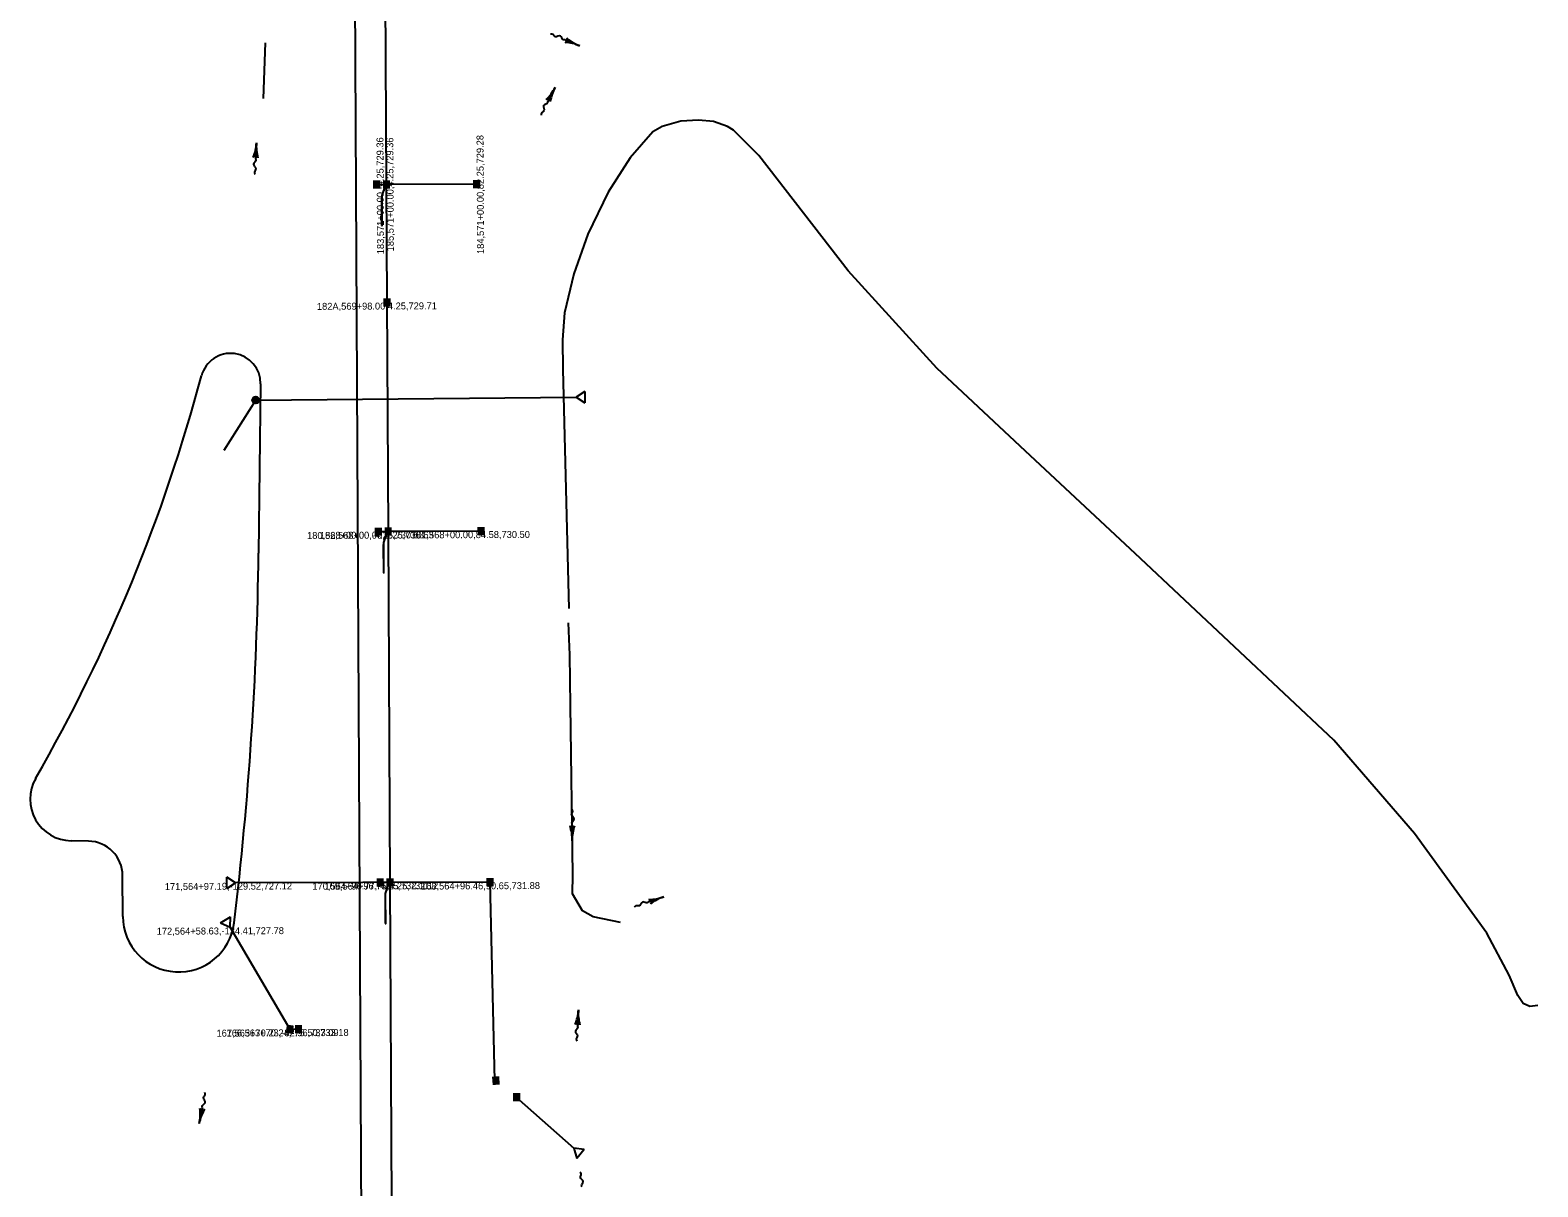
# Model space of a CAD drawing. Extents: x 593481 to 595859, y 101157 to 225994.
# Drawn here: x 594042 to 595346, y 155509 to 156509 of the extents above; entities that cross this region are included whole.
import ezdxf

# ---------------------------------------------------------------- set-up
doc = ezdxf.new("R2010")
doc.units = 0
for name, color, linetype in [('Default', 7, 'Continuous'), ('E_DTM_SpotElev', 7, 'Continuous'), ('E_PROF_GridMin', 7, 'Continuous'), ('Level 6', 7, 'Continuous'), ('P_DRN_SS_UG', 7, 'Continuous'), ('P_MAP_ContoursIndex', 7, 'Continuous'), ('P_MAP_ContoursInter', 7, 'Continuous'), ('P_RDWY_C_and_G_H', 7, 'Continuous')]:
    doc.layers.add(name, color=color, linetype=linetype)

msp = doc.modelspace()

# ---------------------------------------------------------------- linework, layer by layer
at = {"layer": 'Default'}
msp.add_line((594334.5, 154382.7), (594308.8, 159385.6), dxfattribs=at)
at = {"layer": 'E_DTM_SpotElev'}
for p, q in [((594517.4, 156495), (594504.3, 156500.4)), ((594496.2, 156459.2), (594489.7, 156446.7)), ((594238, 156411.3), (594237.2, 156397.2)), ((594510.9, 155808.1), (594511, 155822.3)), ((594590.1, 155759.5), (594576.7, 155755)), ((594516.3, 155661.9), (594515.5, 155647.8)), ((594188.6, 155563.7), (594191.3, 155577.6))]:
    msp.add_line(p, q, dxfattribs=at)
for points in [[(594504.8, 156498.1), (594508.5, 156498.7), (594506.3, 156501.8)], [(594492.1, 156446.9), (594491.8, 156450.7), (594488.6, 156448.8)], [(594239.3, 156398.4), (594237.5, 156401.7), (594235.3, 156398.6)], [(594509, 155820.9), (594511, 155817.7), (594513, 155820.9)], [(594578.6, 155753.5), (594581, 155756.5), (594577.3, 155757.3)], [(594517.6, 155649), (594515.7, 155652.3), (594513.6, 155649.2)], [(594189.1, 155576.7), (594190.4, 155573.2), (594193, 155575.9)]]:
    msp.add_lwpolyline(points, dxfattribs=at)
for centre, start, end in [((594533.4, 156533.8), 229.7798, 247.5421), ((594501.4, 156456.3), 67.5421, 85.3044), ((594458.8, 156478.3), 315.1931, 332.9554), ((594533.5, 156440.2), 152.9554, 170.7177), ((594196.1, 156413.6), 339.0322, 356.7946), ((594279.9, 156408.9), 176.7946, 194.5569), ((594469, 155808.4), 359.6117, 17.374), ((594552.9, 155807.9), 161.8494, 179.6117), ((594576.8, 155799.3), 270.74, 288.5023), ((594603.4, 155719.7), 108.5023, 126.2646), ((594474.4, 155664.2), 339.0322, 356.7946), ((594558.2, 155659.5), 176.7946, 194.5569), ((594147.4, 155571.7), 349.0067, 6.769), ((594229.8, 155555.7), 151.2443, 169.0067)]:
    msp.add_arc(centre, 42, start, end, dxfattribs=at)
for points in [[(594504.3, 156500.4), (594503.5, 156500.4), (594500.9, 156503.6), (594496.4, 156503), (594494.2, 156505), (594492.3, 156505.1)], [(594489.7, 156446.7), (594489.7, 156445.8), (594486.3, 156443.5), (594486.5, 156439), (594484.4, 156436.9), (594484.2, 156435.1)], [(594237.2, 156397.2), (594237.5, 156396.4), (594235.4, 156392.9), (594237.4, 156388.8), (594236.3, 156386), (594236.8, 156384.3)], [(594511, 155822.3), (594510.7, 155823.1), (594512.6, 155826.7), (594510.5, 155830.6), (594511.4, 155833.4), (594510.8, 155835.1)], [(594576.7, 155755), (594576, 155754.5), (594572, 155755.1), (594569, 155751.8), (594566, 155751.8), (594564.6, 155750.6)], [(594515.5, 155647.8), (594515.8, 155647), (594513.7, 155643.5), (594515.6, 155639.4), (594514.5, 155636.7), (594515.1, 155634.9)], [(594191.3, 155577.6), (594191.1, 155578.4), (594193.7, 155581.6), (594192.3, 155585.9), (594193.7, 155588.5), (594193.4, 155590.3)], [(594519.5, 155508.9), (594519.1, 155509.6), (594520.6, 155513.4), (594518.1, 155517.1), (594518.7, 155520), (594517.9, 155521.7)]]:
    msp.add_spline(points, degree=3, dxfattribs=at)
at = {"layer": 'E_PROF_GridMin'}
for p, q in [((594350.5, 156375.2), (594349, 156675.2)), ((594342, 156375.2), (594350.5, 156375.2)), ((594428.5, 156375.6), (594350.5, 156375.2)), ((594352.1, 156075.2), (594350.5, 156375.2)), ((594210.2, 156145.7), (594237.4, 156188.9)), ((594237.4, 156188.9), (594514.4, 156191.3)), ((594343.6, 156075.2), (594352.1, 156075.2)), ((594432.4, 156075.6), (594352.1, 156075.2)), ((594353.6, 155772), (594352.1, 156075.2)), ((594440, 155772.1), (594219.8, 155771.7)), ((594355, 155495.2), (594353.6, 155772)), ((594444.2, 155600.7), (594440, 155772.1)), ((594267.1, 155645), (594215.2, 155733.2)), ((594274.5, 155645.1), (594267, 155645)), ((594462.4, 155586.4), (594512.3, 155542.2))]:
    msp.add_line(p, q, dxfattribs=at)
for points in [[(594245.5, 156497.7), (594243.8, 156449.5)], [(595345.8, 155665.5), (595338.9, 155664.9), (595333.1, 155667.3), (595328.4, 155674.3), (595321, 155691.9), (595301.8, 155728.2), (595239.2, 155814.2), (595169.4, 155895), (594997.8, 156056.2), (594907.2, 156140.8), (594826.3, 156216.4), (594749.6, 156300.6), (594672.2, 156400.2), (594650.5, 156422.2), (594645.2, 156425.4), (594633, 156429.8), (594620.3, 156430.9), (594605, 156429.9), (594588.7, 156425.4), (594580.7, 156420.9), (594561, 156398.2), (594542.2, 156368.7), (594524.6, 156332.4), (594512.5, 156297.9), (594504.2, 156264.4), (594502.7, 156240.9), (594503, 156215.3), (594508, 156008.7)], [(594349.2, 156374.2), (594346.3, 156365.7), (594346.3, 156363.7)], [(594350.7, 156074.2), (594347.9, 156065.7), (594347.9, 156063.7)], [(594552.8, 155737.4), (594529.2, 155742.3), (594520, 155747.6), (594511.1, 155762.2), (594511.5, 155778.5), (594509.6, 155924.8), (594508.9, 155968.8), (594507.7, 155996.4)], [(594352.3, 155771), (594349.4, 155762.5), (594349.4, 155760.5)]]:
    msp.add_lwpolyline(points, dxfattribs=at)
at = {"layer": 'P_DRN_SS_UG'}
for p, q in [((594339.8, 156371.7), (594339.8, 156378.6)), ((594340.7, 156371.7), (594340.7, 156378.6)), ((594341.6, 156371.7), (594341.6, 156378.6)), ((594342.5, 156371.8), (594342.5, 156378.6)), ((594343.4, 156371.8), (594343.4, 156378.6)), ((594344.3, 156371.8), (594344.3, 156378.6)), ((594348.3, 156371.8), (594348.3, 156378.7)), ((594349.2, 156371.8), (594349.2, 156378.7)), ((594350.1, 156371.8), (594350.1, 156378.7)), ((594351, 156371.8), (594351, 156378.7)), ((594351.9, 156371.8), (594351.9, 156378.7)), ((594352.8, 156371.8), (594352.8, 156378.7)), ((594426.3, 156372.2), (594426.3, 156379.1)), ((594427.2, 156372.2), (594427.2, 156379.1)), ((594428.1, 156372.2), (594428.1, 156379.1)), ((594429, 156372.2), (594429, 156379.1)), ((594429.9, 156372.2), (594429.9, 156379.1)), ((594430.8, 156372.2), (594430.8, 156379.1)), ((594348.8, 156269.8), (594348.8, 156276.7)), ((594349.7, 156269.8), (594349.7, 156276.7)), ((594350.6, 156269.8), (594350.6, 156276.7)), ((594351.5, 156269.8), (594351.5, 156276.7)), ((594352.4, 156269.8), (594352.4, 156276.7)), ((594353.3, 156269.8), (594353.3, 156276.7)), ((594341.3, 156071.7), (594341.3, 156078.6)), ((594342.2, 156071.7), (594342.2, 156078.6)), ((594343.1, 156071.8), (594343.1, 156078.6)), ((594344, 156071.8), (594344, 156078.6)), ((594344.9, 156071.8), (594344.9, 156078.6)), ((594345.8, 156071.8), (594345.8, 156078.6)), ((594349.8, 156071.8), (594349.8, 156078.7)), ((594350.7, 156071.8), (594350.7, 156078.7)), ((594351.6, 156071.8), (594351.6, 156078.7)), ((594352.5, 156071.8), (594352.5, 156078.7)), ((594353.4, 156071.8), (594353.4, 156078.7)), ((594354.3, 156071.8), (594354.3, 156078.7)), ((594430.2, 156072.2), (594430.1, 156079)), ((594431.1, 156072.2), (594431, 156079)), ((594432, 156072.2), (594431.9, 156079.1)), ((594432.9, 156072.2), (594432.8, 156079.1)), ((594433.8, 156072.2), (594433.7, 156079.1)), ((594434.7, 156072.3), (594434.6, 156079.1)), ((594342.9, 155768.5), (594342.9, 155775.4)), ((594343.8, 155768.5), (594343.8, 155775.4)), ((594344.7, 155768.5), (594344.7, 155775.4)), ((594345.6, 155768.5), (594345.6, 155775.4)), ((594346.5, 155768.5), (594346.5, 155775.4)), ((594347.4, 155768.5), (594347.4, 155775.4)), ((594351.4, 155768.5), (594351.4, 155775.4)), ((594352.3, 155768.5), (594352.3, 155775.4)), ((594353.2, 155768.5), (594353.2, 155775.4)), ((594354.1, 155768.5), (594354.1, 155775.4)), ((594355, 155768.6), (594355, 155775.4)), ((594355.9, 155768.6), (594355.9, 155775.4)), ((594437.8, 155768.7), (594437.8, 155775.6)), ((594438.7, 155768.7), (594438.7, 155775.6)), ((594439.6, 155768.7), (594439.6, 155775.6)), ((594440.5, 155768.7), (594440.5, 155775.6)), ((594441.4, 155768.7), (594441.4, 155775.6)), ((594442.3, 155768.7), (594442.3, 155775.6)), ((594264.5, 155641.8), (594265.2, 155648.7)), ((594265.4, 155641.7), (594266.1, 155648.6)), ((594266.3, 155641.7), (594267, 155648.5)), ((594267.1, 155641.6), (594267.9, 155648.4)), ((594268, 155641.5), (594268.8, 155648.3)), ((594268.9, 155641.4), (594269.6, 155648.2)), ((594272.3, 155641.6), (594272.3, 155648.5)), ((594273.2, 155641.6), (594273.2, 155648.5)), ((594274.1, 155641.6), (594274.1, 155648.5)), ((594275, 155641.6), (594275, 155648.5)), ((594275.9, 155641.6), (594275.9, 155648.5)), ((594276.8, 155641.6), (594276.8, 155648.5)), ((594443.1, 155597.2), (594442.7, 155604.1)), ((594444, 155597.2), (594443.6, 155604.1)), ((594444.9, 155597.3), (594444.5, 155604.2)), ((594445.8, 155597.3), (594445.4, 155604.2)), ((594446.7, 155597.4), (594446.3, 155604.3)), ((594447.6, 155597.4), (594447.2, 155604.3)), ((594460.6, 155589.8), (594460.6, 155582.9)), ((594461.5, 155589.8), (594461.5, 155582.9)), ((594462.4, 155589.8), (594462.4, 155582.9)), ((594463.3, 155589.8), (594463.3, 155582.9)), ((594464.2, 155589.8), (594464.2, 155582.9)), ((594465.1, 155589.8), (594465.1, 155582.9)), ((594460.5, 155586.2), (594463.5, 155586.2))]:
    msp.add_line(p, q, dxfattribs=at)
for points in [[(594343, 156374.2), (594343, 156376.2), (594341, 156376.2), (594341, 156374.2)], [(594351.5, 156374.2), (594351.5, 156376.2), (594349.5, 156376.2), (594349.5, 156374.2)], [(594429.5, 156374.6), (594429.5, 156376.6), (594427.5, 156376.6), (594427.5, 156374.6)], [(594346.2, 156339.7), (594346.7, 156339.7), (594346.6, 156363.7), (594346.1, 156363.7)], [(594352.1, 156272.2), (594352, 156274.2), (594350, 156274.2), (594350.1, 156272.2)], [(594344.6, 156074.2), (594344.6, 156076.2), (594342.6, 156076.2), (594342.6, 156074.2)], [(594353.1, 156074.2), (594353.1, 156076.2), (594351.1, 156076.2), (594351.1, 156074.2)], [(594433.4, 156074.7), (594433.4, 156076.7), (594431.4, 156076.6), (594431.4, 156074.6)], [(594347.8, 156039.7), (594348.2, 156039.7), (594348.1, 156063.7), (594347.6, 156063.7)], [(594346.1, 155771), (594346.1, 155773), (594344.1, 155773), (594344.1, 155771)], [(594354.6, 155771), (594354.6, 155773), (594352.6, 155773), (594352.6, 155771)], [(594441, 155771.1), (594441, 155773.1), (594439, 155773.1), (594439, 155771.1)], [(594349.3, 155736.5), (594349.8, 155736.5), (594349.7, 155760.5), (594349.2, 155760.5)], [(594267.9, 155643.9), (594268.2, 155645.9), (594266.2, 155646.1), (594266, 155644.1)], [(594275.5, 155644.1), (594275.5, 155646.1), (594273.5, 155646.1), (594273.5, 155644.1)], [(594446.2, 155599.8), (594446.1, 155601.8), (594444.1, 155601.7), (594444.2, 155599.7)]]:
    msp.add_lwpolyline(points, close=True, dxfattribs=at)
at = {"layer": 'P_MAP_ContoursIndex'}
for p, q in [((594241.6, 156203), (594239.8, 156056.5)), ((594092.9, 155807.7), (594077.7, 155808)), ((594122.5, 155742.7), (594122.3, 155777.9))]:
    msp.add_line(p, q, dxfattribs=at)
for centre, radius, start, end in [((594215.6, 156203.3), 26, 359.2941, 165.091), ((592792.2, 156582.3), 1447, 330.142, 345.091), ((591269.1, 156093.1), 2971, 353.1195, 359.2941), ((594078.4, 155844), 36, 150.142, 268.9825), ((594092.3, 155777.7), 30, 0.2941, 88.9825), ((594170.8, 155742.9), 48.3, 180.2941, 353.1195)]:
    msp.add_arc(centre, radius, start, end, dxfattribs=at)
at = {"layer": 'P_MAP_ContoursInter'}
for radius in [2.98, 2.4, 1.8, 1.2, 0.6]:
    msp.add_circle((594237.4, 156188.9), radius, dxfattribs=at)
at = {"layer": 'P_RDWY_C_and_G_H'}
for p, q in [((594521.9, 156196.4), (594514.4, 156191.3)), ((594514.4, 156191.3), (594521.9, 156186.4)), ((594521.9, 156196.4), (594521.9, 156186.4)), ((594219.8, 155771.7), (594212.3, 155776.7)), ((594212.4, 155766.7), (594212.3, 155776.7)), ((594212.4, 155766.7), (594219.8, 155771.7)), ((594207, 155737.1), (594215.7, 155742.2)), ((594207, 155737.1), (594215.2, 155733.2)), ((594215.2, 155733.2), (594215.7, 155742.2)), ((594521.3, 155541.2), (594512.3, 155542.2)), ((594512.3, 155542.2), (594514.9, 155533.5)), ((594521.3, 155541.2), (594514.9, 155533.5))]:
    msp.add_line(p, q, dxfattribs=at)

# ---------------------------------------------------------------- texts
at = {"layer": 'Level 6'}
for s, rotation, p in [('183,571+00.00,-4.25,729.36', 90.2941, (594348.3, 156315)), ('185,571+00.00,4.25,729.36', 90.2941, (594356.8, 156317.5)), ('184,571+00.00,82.25,729.28', 90.2941, (594434.8, 156315.2)), ('182A,569+98.00,4.25,729.71', 0.2941, (594290.3, 156266.9)), ('180,568+00.00,-4.25,730.63', 0.2941, (594281.8, 156068.9)), ('182,568+00.00,4.25,730.63', 0.2941, (594292.9, 156068.9)), ('181,568+00.00,84.58,730.50', 0.2941, (594371.6, 156069.3)), ('171,564+97.19,-129.52,727.12', 0.2941, (594158.8, 155765.4)), ('170,564+96.77,-4.25,732.11', 0.2941, (594286.4, 155765.7)), ('169,564+96.75,4.25,732.12', 0.2941, (594296.8, 155765.7)), ('168,564+96.46,90.65,731.88', 0.2941, (594380.3, 155765.8)), ('172,564+58.63,-134.41,727.78', 0.2941, (594151.8, 155726.8)), ('167,563+70.23,-82.96,733.09', 0.2941, (594203.5, 155638.7)), ('166,563+70.24,-75.50,733.18', 0.2941, (594212.2, 155638.8))]:
    msp.add_text(s, height=6, rotation=rotation, dxfattribs=at).set_placement(p)

doc.saveas('drawing.dxf')
